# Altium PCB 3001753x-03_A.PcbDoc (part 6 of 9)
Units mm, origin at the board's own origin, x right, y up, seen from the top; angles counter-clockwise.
Board outline 210 x 130 mm, 8 copper layers (1-TOP, 2-GND, 3-INTOP, 4-PWR, 5-PWR, 6-INBOT, 7-GND, 8-BOTTOM), stack 1.646 mm thick; 676 components, 623 nets, 2861 pads, 2382 vias.
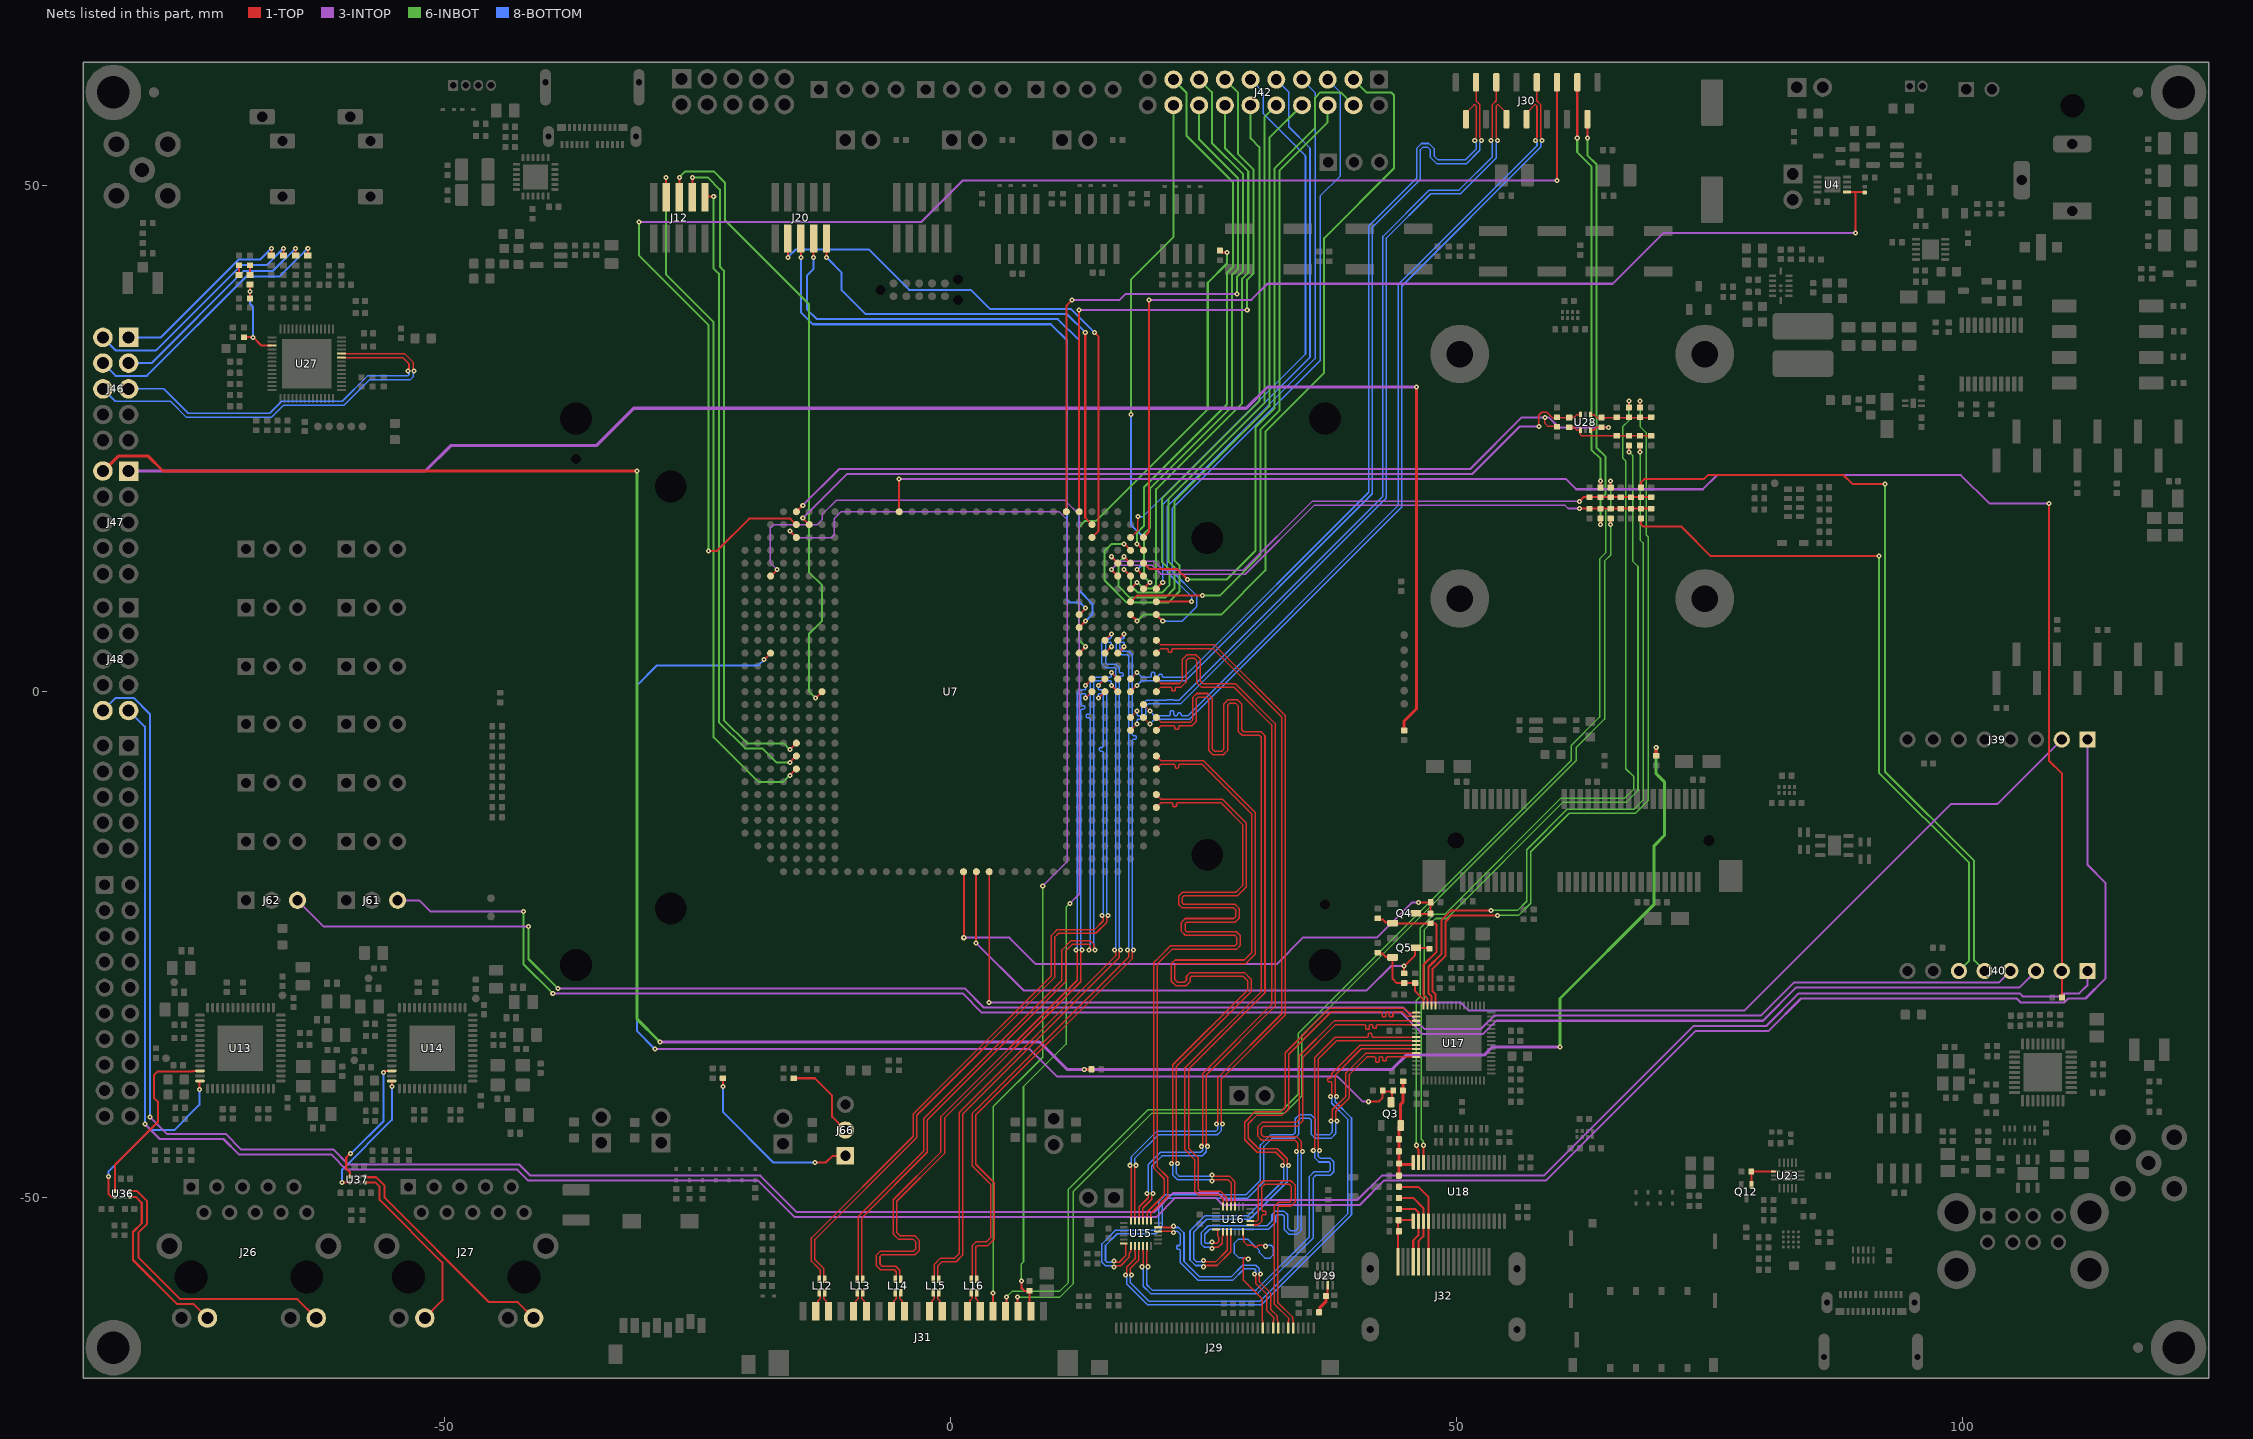
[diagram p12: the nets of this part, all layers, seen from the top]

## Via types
v1: diameter 0.5, hole 0.2, 1-TOP to 8-BOTTOM, 1547 vias
v2: diameter 0.68, hole 0.3, 1-TOP to 8-BOTTOM, 835 vias

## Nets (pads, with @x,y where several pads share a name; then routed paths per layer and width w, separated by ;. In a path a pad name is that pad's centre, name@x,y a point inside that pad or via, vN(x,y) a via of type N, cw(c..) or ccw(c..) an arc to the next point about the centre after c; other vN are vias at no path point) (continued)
HDMI_FIL_SCL: J32.15 R128.2 U18.22 | length 8.3
  1-TOP w0.2: R128.2@44.28,-50 45.7,-50 46.7,-51 U18.22@46.7,-52.3 46.7,-53.8 46.2,-54.3 J32.15@46.2,-56.3
HDMI_FIL_SDA: J32.16 R129.2 U18.21 | length 7.2
  1-TOP w0.2: R129.2@44.28,-51.1 45.9,-51.1 46.2,-51.4 U18.21@46.2,-52.3 46.2,-53.7 45.7,-54.2 J32.16@45.7,-56.3
HDMI_HPD_1V8: C115.2 Q3.S R121.1 R127.2 R130.1 R132.1 R244.1 U18.19 | length 10.9
  1-TOP w0.2: R244.1@44.28,-47.8 R244.1@44.305,-47.775
  1-TOP w0.3: R244.1@44.305,-47.775 C115.2@44.305,-46.6 44.305,-45.425 R127.2@44.28,-45.4 R130.1@44.28,-44.2 44.28,-43.02 Q3.S@44.45,-42.85 ; C115.2@44.46,-46.6 44.46,-46.7 U18.19@45.7,-46.7 ; Q3.S@44.46,-42.85 44.46,-40.74 44.7,-40.5 44.7,-39.42 R132.1@44.68,-39.4 ; R132.1@44.7,-39.4 R121.1@44.7,-38.4
HDMI_HPD_3V3_CPU: Q3.D R131.1 R132.2 U7.C18 | length 128.2
  1-TOP w0.2: v1(-18.415,3.175) U7.C18@-17.78,3.81 ; v1(41.3,-40.5) 42.3,-40.5 42.68,-40.12 R131.1@42.68,-39.5 ; R131.1@42.68,-39.4 R131.1@42.68,-39.5 ; Q3.D@43.5,-40.65 43.62,-40.53 43.62,-39.5 R131.1@42.68,-39.5
  3-INTOP w0.2: v1(-29.2,-35.3) 7.8,-35.3 10.5,-38 38.2,-38 40.7,-40.5 v1(41.3,-40.5)
  8-BOTTOM w0.2: v1(-29.2,-35.3) -31,-33.5 -31,0.6 -29,2.6 -18.99,2.6 v1(-18.415,3.175)
HDMI_SCL_1V8: R185.2 U18.17 | length 84.5
  1-TOP w0.2: U18.17@46.7,-46.5 v1(46.7,-44.8) ; v1(67,23.7) R185.2@67,24.32
  6-INBOT w0.15: v1(46.7,-44.8) 46.7,-44.4 46.5,-44.2 46.5,-30.7 46.8,-30.4 46.8,-23.5 47.9,-22.4 49,-22.4 60.5,-10.9 66.766,-10.9 67.9,-9.766 67.9,12.373 67.4,12.873 67.4,23.3 v1(67,23.7)
HDMI_SDA_1V8: R187.2 U18.18 | length 89.8
  1-TOP w0.2: v1(46,-44.8) 46,-45 46.2,-45.2 U18.18@46.2,-46.5 ; R187.2@67,28.08 v1(67,28.7)
  6-INBOT w0.15: v1(46,-44.8) 46,-30.5 46.4,-30.1 46.4,-23.334 47.734,-22 48.8,-22 60.3,-10.5 66.6,-10.5 67.5,-9.6 67.5,-8.4 66.7,-7.6 66.7,22.8 66.4,23.1 66.4,24.3 66.4,26.2 67,26.8 v1(67,28.7)
HDMICEC: J32.13 R120.2 U18.23 | length 9.7
  1-TOP w0.2: R120.2@44.28,-48.9 46.2,-48.9 47.2,-49.9 U18.23@47.2,-52.3 J32.13@47.2,-56.3
HDMIHPD: C119.2 J32.19 R126.2 U18.20 | length 5.6
  1-TOP w0.2: J32.19@44.2,-56.3 44.2,-52.26 C119.2@44.26,-52.2 45.6,-52.2 U18.20@45.7,-52.3
I2C3_SCL: R46.1 R48.1 R178.1 R180.1 R184.1 R188.1 R230.1 U7.AK25 | length 57.8
  1-TOP w0.2: v1(15.875,13.335) U7.AK25@16.51,12.7 ; v1(62.1,18.8) 62.52,19.22 R180.1@63.1,19.22 R184.1@64.2,19.22 R178.1@65.2,19.22 R188.1@66.2,19.22 R46.1@67.2,19.22 R48.1@68.2,19.22 R230.1@69.2,19.22
  3-INTOP w0.15: v1(15.875,13.335) 16.31,12.9 20.1,12.9 21,12 28.9,12 35.7,18.8 v1(62.1,18.8)
I2C3_SDA: R47.1 R49.1 R181.1 R182.1 R186.1 R190.1 R231.1 U7.AK24 | length 57.8
  1-TOP w0.2: v1(15.875,12.065) U7.AK24@16.51,11.43 ; v1(62.1,18.1) 62.12,18.08 R181.1@63.1,18.08 R186.1@64.2,18.08 64.22,18.1 65.18,18.1 R182.1@65.2,18.08 65.22,18.1 R231.1@69.2,18.1
  3-INTOP w0.15: v1(15.875,12.065) 16.31,12.5 19.9,12.5 20.8,11.6 29.1,11.6 35.9,18.4 60.7,18.4 61,18.1 v1(62.1,18.1)
I2C4_SCL: R173.1 R176.2 U7.F28 U28.6 | length 83
  1-TOP w0.15: v1(58.1,26.2) 58.1,27.3 58.4,27.6 58.9,27.6 59.42,27.08 R176.2@61.1,27.08 61.12,27.1 61.6,27.1 61.88,27.38 U28.6@62.2,27.38
  1-TOP w0.2: v1(-14.605,17.145) U7.F28@-13.97,16.51
  3-INTOP w0.2: v1(-14.605,17.145) -10.25,21.5 51.5,21.5 56.2,26.2 v1(58.1,26.2)
I2C4_SCL_1V8: R172.1 R176.1 R179.1 R185.1 R189.1 U28.1 | length 8.7
  1-TOP w0.15: R176.1@61.1,26.12 61.12,26.1 61.6,26.1 61.88,25.82 U28.1@62.2,25.82 62.2,25.4 62.32,25.28 R172.1@65.8,25.28 R185.1@67,25.28 R189.1@68.1,25.28 R179.1@69.2,25.28
I2C4_SDA: R175.1 R177.2 U7.E29 U28.3 | length 88.4
  1-TOP w0.15: v1(58.7,27.1) 58.7,26.5 59,26.2 R175.1@59.9,26.2 ; U28.3@63.2,25.82 63.52,25.82 63.82,26.12 R177.2@64.3,26.12
  1-TOP w0.2: U7.E29@-15.24,17.78 v1(-14.605,18.415) ; R177.2@64.3,26.12 64.32,26.1 v1(65,26.1)
  3-INTOP w0.2: v1(-14.605,18.415) -11.02,22 51.327,22 56.427,27.1 v1(58.7,27.1) 59.1,27.1 60.1,26.1 v1(65,26.1)
I2C4_SDA_1V8: R174.1 R177.1 R183.1 R187.1 R191.1 U28.4 | length 6.1
  1-TOP w0.15: U28.4@63.2,27.38 63.52,27.38 63.82,27.08 R177.1@64.3,27.08 65.8,27.08 67,27.08 68.1,27.08 R183.1@69.2,27.08
I3C2_SCL: J66.1 R104.1 | length 17.8
  1-TOP w0.2: v1(-22.5,-39) R104.1@-22.5,-38.18 ; v1(-13.4,-46.5) -12.314,-46.5 -11.654,-45.84 J66.1@-10.4,-45.84
  8-BOTTOM w0.2: v1(-22.5,-39) -22.5,-41.5 -17.5,-46.5 v1(-13.4,-46.5)
I3C2_SDA: J66.2 R241.1 | length 8.5
  1-TOP w0.2: R241.1@-15.5,-38.18 -13.42,-38.18 -11.7,-39.9 -11.7,-42 J66.2@-10.4,-43.3
ILIM_5V_VBUS: Q12.G R202.2 U23.6 | length 3.7
  1-TOP w0.2: Q12.G@79.1,-48.71 79.1,-47.42 R202.2@79.08,-47.4 U23.6@81.45,-47.4
IMX9_ON_OFF: R4.2 U7.AG18 | length 47.6
  1-TOP w0.2: U7.AG18@12.7,3.81 v1(13.335,4.445) ; R4.2@26.6,43.58 26.775,43.405 27.295,43.405 v1(27.3,43.4)
  6-INBOT w0.2: v1(13.335,4.445) 12.7,5.08 12.7,15.2 12.7,16.3 13.25,16.85 14.35,16.85 25.4,27.9 25.4,40.4 27.3,42.3 v1(27.3,43.4)
IW612_JTAG_TCK: J12.3 U7.E11 | length 66.4
  1-TOP w0.2: J12.3@-25.53,48.832 -25.5,48.862 v1(-25.5,50.8) ; v1(-15.875,-5.715) U7.E11@-15.24,-5.08
  6-INBOT w0.2: v1(-25.5,50.8) -24,50.8 -22.8,49.6 -22.8,42 -22.4,41.6 -22.4,-2.8 -20.1,-5.1 -16.49,-5.1 v1(-15.875,-5.715)
IW612_JTAG_TDI: J12.7 U7.E9 | length 69.8
  1-TOP w0.2: v1(-28.1,50.8) -28.1,48.862 J12.7@-28.07,48.832 ; v1(-15.875,-8.255) U7.E9@-15.24,-7.62
  6-INBOT w0.2: v1@-28.1,50.9 -28.1,41.2 -23.4,36.5 -23.4,-4.5 -19,-8.9 -16.52,-8.9 v1(-15.875,-8.255)
IW612_JTAG_TDO: J12.5 U7.G15 | length 63.8
  1-TOP w0.2: J12.5@-26.8,48.832 v1(-26.8,50.8) ; v1(-13.335,-0.635) U7.G15@-12.7,0
  6-INBOT w0.2: v1(-26.8,50.8) -26.2,51.4 -23.4,51.4 -22.3,50.3 -22.3,46.6 -14,38.3 -14,11.8 -12.7,10.5 -12.7,7 -14,5.7 -14,0.03 v1(-13.335,-0.635)
IW612_JTAG_TMS: J12.1 U7.E10 | length 62.6
  1-TOP w0.2: J12.1@-24.26,48.832 -24.26,48.9 v1(-23.4,48.9) ; v1(-15.875,-6.985) U7.E10@-15.24,-6.35
  6-INBOT w0.2: v1(-23.4,48.9) -23.4,46.6 -23.4,41.8 -22.9,41.3 -22.9,-3 -20.3,-5.6 -18.6,-5.6 -17.215,-6.985 v1(-15.875,-6.985)
JTAG_TCK: J20.4 U7.AG20 | length 64.9
  1-TOP w0.2: v1(-13.53,42.9) J20.4@-13.53,44.768 ; U7.AG20@12.7,6.35 v1(13.335,6.985)
  8-BOTTOM w0.2: v1(-13.53,42.9) -13.53,41.77 -14.2,41.1 -14.2,37.8 -13.2,36.8 10.6,36.8 12.7,34.7 12.7,10 14,8.7 14,7.65 v1(13.335,6.985)
JTAG_TDI: J20.8 U7.AH27 | length 56.6
  1-TOP w0.2: v1(-16.07,42.9) J20.8@-16.07,44.768 ; U7.AH27@13.97,15.24 14.6,15.87 14.6,35.1 v1(14.2,35.5)
  8-BOTTOM w0.2: v1(-16.07,42.9) -15.27,43.7 -8.1,43.7 -4.1,39.7 2,39.7 3.9,37.8 11.9,37.8 v1(14.2,35.5)
JTAG_TDO: J20.6 U7.AG21 | length 63.4
  1-TOP w0.2: v1(-14.8,42.9) J20.6@-14.8,44.768 ; U7.AG21@12.7,7.62 v1(13.335,8.255)
  8-BOTTOM w0.2: v1(-14.8,42.9) -14.8,41.5 -14.8,37.5 -13.6,36.3 9.9,36.3 11.5,34.7 11.5,9.1 11.8,8.8 12.79,8.8 v1(13.335,8.255)
JTAG_TMS: J20.2 U7.AH28 | length 50.8
  1-TOP w0.2: v1(-12.26,42.9) J20.2@-12.26,44.768 ; v1(13.3,35.5) 13.3,17.18 U7.AH28@13.97,16.51
  8-BOTTOM w0.2: v1(-12.26,42.9) -10.76,41.4 -10.76,39.66 -8.4,37.3 11.5,37.3 v1(13.3,35.5)
L_CLK_N: J31.11 L15.2 | length 2
  1-TOP w0.15: J31.11@-1.85,-61.25 -1.85,-60.15 -1.627,-59.927 -1.627,-59.498 L15.2@-1.725,-59.4
L_CLK_P: J31.12 L15.3 | length 2
  1-TOP w0.15: L15.3@-1.175,-59.4 -1.273,-59.498 -1.273,-59.927 -1.05,-60.15 J31.12@-1.05,-61.25
L_D0_N: J31.2 L12.2 | length 2
  1-TOP w0.15: J31.2@-13.1,-61.25 -13.1,-60.15 -12.877,-59.927 -12.877,-59.498 L12.2@-12.975,-59.4
L_D0_P: J31.3 L12.3 | length 2
  1-TOP w0.15: L12.3@-12.425,-59.4 -12.523,-59.498 -12.523,-59.927 -12.3,-60.15 J31.3@-12.3,-61.25
L_D1_N: J31.5 L13.2 | length 2
  1-TOP w0.15: J31.5@-9.35,-61.25 -9.35,-60.15 -9.127,-59.927 -9.127,-59.498 L13.2@-9.225,-59.4
L_D1_P: J31.6 L13.3 | length 2
  1-TOP w0.15: L13.3@-8.675,-59.4 -8.773,-59.498 -8.773,-59.927 -8.55,-60.15 J31.6@-8.55,-61.25
L_D2_N: J31.8 L14.2 | length 2
  1-TOP w0.15: J31.8@-5.6,-61.25 -5.6,-60.15 -5.377,-59.927 -5.377,-59.498 L14.2@-5.475,-59.4
L_D2_P: J31.9 L14.3 | length 2
  1-TOP w0.15: L14.3@-4.925,-59.4 -5.023,-59.498 -5.023,-59.927 -4.8,-60.15 J31.9@-4.8,-61.25
L_D3_N: J31.14 L16.2 | length 2
  1-TOP w0.15: J31.14@1.9,-61.25 1.9,-60.15 2.123,-59.927 2.123,-59.498 L16.2@2.025,-59.4
L_D3_P: J31.15 L16.3 | length 2
  1-TOP w0.15: L16.3@2.575,-59.4 2.477,-59.498 2.477,-59.927 2.7,-60.15 J31.15@2.7,-61.25
LDO2: J47.1 R36.1 | length 164.9
  1-TOP w0.3: R36.1@44.8,-3.82 44.8,-2.9 46,-1.7 v1(46,30.1)
  3-INTOP w0.3: J47.1@-81.1,21.82 -51.87,21.82 -49.39,24.3 -35,24.3 -31.3,28 29.2,28 31.3,30.1 v1(46,30.1)
LDO3: J47.2 R37.1 R243.1 | length 237.9
  1-TOP w0.3: J47.2@-83.64,21.82 -82.16,23.3 -79.3,23.3 -77.8,21.8 v1(-31,21.8) ; v1(13.2,-37.3) R37.1@13.92,-37.3 ; R243.1@69.7,-6.32 v1(69.7,-5.5)
  3-INTOP w0.3: v1(-28.7,-34.6) 8.8,-34.6 11.5,-37.3 v1(13.2,-37.3) 43.6,-37.3 45,-35.9 52.7,-35.9 53.5,-35.1 v1(60.2,-35.1)
  6-INBOT w0.3: v1(-31,21.8) -31,-32.3 v1(-28.7,-34.6) ; v1(60.2,-35.1) 60.2,-30.3 69.5,-21 69.5,-15.2 70.5,-14.2 70.5,-8.9 69.7,-8.1 v1(69.7,-5.5)
LED: R212.2 R217.1 U29.7 | length 3.1
  1-TOP w0.2: R212.2@36.28,-61.4 36.28,-61.32 R212.2@36.5,-61.1 ; R217.1@37.18,-59.7 37.25,-59.63 U29.7@37.25,-58.635
  1-TOP w0.3: R212.2@36.5,-61.1 36.5,-60.8 37.1,-60.2 R217.1@37.1,-59.7
LED_1_1000_1V8: U13.12 U36.4 | length 18.1
  1-TOP w0.2: U36.4@-82.55,-49.3 -82.55,-46.75 -78.3,-42.5 -78.3,-40.5 -78.7,-40.1 -78.7,-37.9 -78.3,-37.5 -74.85,-37.5 -74.8,-37.45 U13.12@-74.15,-37.45
LED_1_1000_3V3: J26.D4 U36.1 | length 28
  1-TOP w0.2: U36.1@-81.05,-49.3 -80.4,-49.3 -80.2,-49.5 -79.4,-50.3 -79.4,-52.6 -80.2,-53.4 -80.2,-55.9 -76.1,-60 -64.524,-60 J26.D4@-62.66,-61.864
LED_1_ACT_1V8: U13.14 U36.5 | length 17.1
  1-TOP w0.2: v1@-83.156,-47.944 v1(-83.2,-47.9) -83.2,-49.6 -82.9,-49.9 U36.5@-82.55,-49.9 ; v1(-74.2,-39.3) -74.2,-38.5 U13.14@-74.15,-38.45
  8-BOTTOM w0.2: v1(-83.2,-47.9) -83.2,-47.4 -79.1,-43.3 -76.7,-43.3 -74.2,-40.8 v1(-74.2,-39.3)
LED_1_ACT_3V3: J26.D2 U36.8 | length 17.1
  1-TOP w0.2: U36.8@-81.05,-49.9 -80.5,-49.9 -79.9,-50.5 -79.9,-52.5 -80.766,-53.366 -80.766,-56.134 -76.4,-60.5 -74.774,-60.5 J26.D2@-73.41,-61.864
LED_2_1000_1V8: U14.12 U37.4 | length 12.9
  1-TOP w0.2: U37.4@-59.35,-47.9 -59.35,-47.445 -59.7,-47.095 -59.7,-46 v1(-59.3,-45.6) ; v1(-56,-37.6) -55.85,-37.45 U14.12@-55.2,-37.45
  8-BOTTOM w0.2: v1(-59.3,-45.6) -59.219,-45.6 -59.08,-45.461 -59.061,-45.461 -56,-42.4 v1(-56,-37.6)
LED_2_1000_3V3: J27.D4 U37.1 | length 23.2
  1-TOP w0.2: U37.1@-57.85,-47.9 -57.85,-47.91 -57.8,-47.96 -56.74,-47.96 -55.9,-48.8 -55.9,-50 -45.6,-60.3 -42.754,-60.3 J27.D4@-41.19,-61.864
LED_2_ACT_1V8: U14.14 U37.5 | length 12.8
  1-TOP w0.2: v1(-60.1,-48.5) U37.5@-59.35,-48.5 ; v1(-55.2,-39) U14.14@-55.2,-38.45
  8-BOTTOM w0.2: v1(-60.1,-48.5) -60.1,-47.2 -55.2,-42.3 v1(-55.2,-39)
LED_2_ACT_3V3: J27.D2 U37.8 | length 17.9
  1-TOP w0.2: U37.8@-57.85,-48.5 -56.8,-48.5 -56.4,-48.9 -56.4,-50.2 -50.2,-56.4 -50.2,-60.124 J27.D2@-51.94,-61.864
LINE1_IN_L: J46.2 L35.1 | length 23.3
  1-TOP w0.2: L35.1@-65.9,43.08 v1(-65.9,43.8)
  8-BOTTOM w0.2: J46.2@-83.74,35 -82.44,33.7 -78.5,33.7 -70.069,42.131 -67.569,42.131 v1(-65.9,43.8)
LINE1_IN_R: J46.1 L34.1 | length 18.5
  1-TOP w0.2: L34.1@-67.1,43.08 v1(-67.1,43.8)
  8-BOTTOM w0.2: J46.1@-81.2,35 -78,35 -70.303,42.697 -68.203,42.697 v1(-67.1,43.8)
LINE2_IN_L: J46.4 L37.1 | length 26.7
  1-TOP w0.2: L37.1@-63.5,43.08 v1(-63.5,43.8)
  8-BOTTOM w0.2: J46.4@-83.74,32.46 -82.48,31.2 -79.4,31.2 -69.6,41 -66.3,41 v1(-63.5,43.8)
LINE2_IN_R: J46.3 L36.1 | length 21.9
  1-TOP w0.2: L36.1@-64.7,43.08 v1(-64.7,43.8)
  8-BOTTOM w0.2: J46.3@-81.2,32.46 -78.94,32.46 -69.834,41.566 -66.934,41.566 v1(-64.7,43.8)
LINE_OUT_L: J46.6 U27.24 | length 42.4
  1-TOP w0.15: U27.24@-60.17,33.4 -59,33.4 -53.934,33.4 -53.1,32.566 -53.1,31.8 v1(-53,31.7)
  8-BOTTOM w0.15: J46.6@-83.74,29.92 -82.52,28.7 -77.066,28.7 -75.466,27.1 -67.1,27.1 -65.9,28.3 -59.934,28.3 -57.434,30.8 -53.4,30.8 -53.1,31.1 -53.1,31.6 v1(-53,31.7)
LINE_OUT_R: J46.5 U27.23 | length 38.4
  1-TOP w0.15: U27.23@-60.17,33 -54.1,33 -53.5,32.4 -53.5,31.8 v1(-53.6,31.7)
  8-BOTTOM w0.15: J46.5@-81.2,29.92 -77.72,29.92 -75.3,27.5 -67.266,27.5 -66.066,28.7 -60.1,28.7 -57.6,31.2 -53.6,31.2 -53.5,31.3 -53.5,31.6 v1(-53.6,31.7)
LT8912B_CLK_N: U15.16 U17.8 | length 54.6
  1-TOP w0.15: v1(18.9,-56.8) 19.023,-56.677 19.023,-55.323 19,-55.3 U15.16@19,-54.745 ; v1(36.423,-45.3) 36.3,-45.177 36.3,-36.301 38.124,-34.477 45.972,-34.477 U17.8@45.995,-34.5
  8-BOTTOM w0.15: v1(18.9,-56.8) 19.023,-56.923 19.023,-58.723 19.754,-59.454 ; 19.78,-59.454 30.322,-59.454 35.8,-53.976 35.8,-48.026 36.072,-47.754 37.512,-47.754 37.85,-47.416 37.85,-46.422 37.528,-46.1 36.525,-46.1 36.3,-45.875 36.3,-45.423 v1(36.423,-45.3)
LT8912B_CLK_P: U15.17 U17.7 | length 54.6
  1-TOP w0.15: U15.17@19.4,-54.745 19.4,-55.3 19.377,-55.323 19.377,-56.677 v1(19.5,-56.8) ; v1(35.823,-45.3) 35.946,-45.177 35.946,-36.154 37.977,-34.123 41.1,-34.123 41.175,-34.123 41.263,-34.035 41.263,-33.807 41.333,-33.737 41.543,-33.737 41.613,-33.807 41.613,-34.035 41.701,-34.123 41.8,-34.123 43.6,-34.123 45.972,-34.123 U17.7@45.995,-34.1
  8-BOTTOM w0.15: v1(19.5,-56.8) 19.377,-56.923 19.377,-58.576 19.901,-59.1 ; 19.926,-59.1 30.175,-59.1 35.446,-53.829 35.446,-47.879 35.925,-47.4 37.365,-47.4 37.496,-47.269 37.496,-46.569 37.381,-46.454 36.378,-46.454 35.946,-46.022 35.946,-45.423 v1(35.823,-45.3)
LT8912B_D0_N: U16.14 U17.2 | length 54.6
  1-TOP w0.15: v1(25,-56.2) 25.123,-56.323 26.176,-56.323 27.323,-55.176 27.323,-53.827 27.321,-53.825 27.321,-53.366 U16.14@27.3,-53.345 ; v1(33.377,-46.8) 33.254,-46.677 33.254,-46.129 32.271,-45.146 30.446,-45.146 29.4,-44.1 29.4,-42.676 30.222,-41.854 32.746,-41.854 33.4,-41.2 33.4,-35.801 37.597,-31.604 42.136,-31.604 42.561,-31.604 42.649,-31.692 42.649,-32.074 42.701,-32.126 42.946,-32.126 42.999,-32.074 42.999,-31.657 43.051,-31.604 43.296,-31.604 43.349,-31.657 43.349,-32.056 43.401,-32.109 43.646,-32.109 43.699,-32.056 43.699,-31.692 43.787,-31.604 44.25,-31.604 44.63,-31.604 45.103,-32.077 45.972,-32.077 U17.2@45.995,-32.1
  8-BOTTOM w0.15: v1(25,-56.2) 24.877,-56.323 24.323,-56.323 24,-56 24,-53.4 25.3,-52.1 29.55,-52.1 33.254,-48.396 33.254,-46.923 v1(33.377,-46.8)
LT8912B_D0_P: U16.15 U17.1 | length 54.6
  1-TOP w0.15: v1(25,-56.8) 25.123,-56.677 26.323,-56.677 27.677,-55.323 27.677,-53.368 U16.15@27.7,-53.345 ; v1(32.777,-46.8) 32.9,-46.677 32.9,-46.276 32.124,-45.5 30.299,-45.5 29.046,-44.247 29.046,-42.529 30.075,-41.5 32.599,-41.5 33.046,-41.053 33.046,-35.654 37.45,-31.25 44.777,-31.25 45.25,-31.723 45.972,-31.723 U17.1@45.995,-31.7
  8-BOTTOM w0.15: v1(25,-56.8) 24.877,-56.677 24.176,-56.677 23.646,-56.147 23.646,-53.253 25.153,-51.746 29.403,-51.746 32.9,-48.249 32.9,-46.923 v1(32.777,-46.8)
LT8912B_D1_N: U16.12 U17.4 | length 54.5
  1-TOP w0.15: v1(25.8,-54.377) 25.8,-54.4 25.9,-54.5 26.299,-54.5 26.473,-54.326 26.473,-53.873 26.4,-53.8 U16.12@26.4,-53.1 ; v1(34.777,-45.4) 34.654,-45.277 34.654,-44.429 34.171,-43.946 30.878,-43.946 30.675,-43.743 30.675,-43.136 30.911,-42.9 34.275,-42.9 34.8,-42.375 34.8,-36.101 38.024,-32.877 40.5,-32.877 40.925,-32.877 41.013,-32.965 41.013,-33.292 41.065,-33.345 41.31,-33.345 41.363,-33.292 41.363,-32.929 41.415,-32.877 41.66,-32.877 41.713,-32.929 41.713,-33.197 41.765,-33.249 42.01,-33.249 42.063,-33.197 42.063,-32.965 42.151,-32.877 42.25,-32.877 43.8,-32.877 45.972,-32.877 U17.4@45.995,-32.9
  8-BOTTOM w0.15: v1(25.8,-54.377) 25.677,-54.5 25.2,-54.5 25.1,-54.4 25.1,-53.601 25.601,-53.1 29.5,-53.1 31.401,-53.1 32.1,-52.401 32.1,-51.801 32.247,-51.654 32.79,-51.654 32.946,-51.81 32.946,-53.119 33.427,-53.6 34.229,-53.6 34.654,-53.175 34.654,-51.947 34.654,-45.523 v1(34.777,-45.4)
LT8912B_D1_P: U16.13 U17.3 | length 54.6
  1-TOP w0.15: v1(25.8,-54.977) 25.8,-54.954 25.9,-54.854 26.173,-54.854 26.446,-54.854 26.827,-54.473 26.827,-53.873 26.9,-53.8 U16.13@26.9,-53.345 ; v1(34.177,-45.4) 34.3,-45.277 34.3,-44.576 34.024,-44.3 30.731,-44.3 30.321,-43.89 30.321,-42.989 30.764,-42.546 34.128,-42.546 34.446,-42.228 34.446,-35.954 37.877,-32.523 45.972,-32.523 U17.3@45.995,-32.5
  8-BOTTOM w0.15: v1(25.8,-54.977) 25.677,-54.854 25.053,-54.854 24.746,-54.547 24.746,-53.454 25.454,-52.746 31.254,-52.746 31.746,-52.254 31.746,-51.654 32.1,-51.3 32.937,-51.3 33.3,-51.663 33.3,-52.972 33.574,-53.246 34.082,-53.246 34.3,-53.028 34.3,-45.523 v1(34.177,-45.4)
LT8912B_D2_N: U15.14 U17.10 | length 54.6
  1-TOP w0.15: v1(17.277,-57.6) 17.4,-57.477 17.4,-56.823 18.223,-56 18.223,-55.323 18.2,-55.3 U15.14@18.2,-54.745 ; v1(38.123,-40) 38,-39.877 38,-37.85 40.573,-35.277 43.6,-35.277 45.972,-35.277 U17.10@45.995,-35.3
  8-BOTTOM w0.15: v1(17.277,-57.6) 17.4,-57.723 17.4,-58.501 19.453,-60.554 ; 19.479,-60.554 30.721,-60.554 39.6,-51.675 39.6,-42.099 38,-40.499 38,-40.123 v1(38.123,-40)
LT8912B_D2_P: U15.15 U17.9 | length 54.6
  1-TOP w0.15: v1(17.877,-57.6) 17.754,-57.477 17.754,-56.97 18.577,-56.147 18.577,-55.323 18.6,-55.3 U15.15@18.6,-54.745 ; v1(37.523,-40) 37.646,-39.877 37.646,-38.605 37.558,-38.517 37.33,-38.517 37.26,-38.447 37.26,-38.237 37.33,-38.167 37.558,-38.167 37.646,-38.079 37.646,-37.9 37.646,-37.703 40.426,-34.923 45.972,-34.923 U17.9@45.995,-34.9
  8-BOTTOM w0.15: v1(17.877,-57.6) 17.754,-57.723 17.754,-58.354 19.6,-60.2 ; 19.626,-60.2 30.574,-60.2 39.246,-51.528 39.246,-42.246 37.646,-40.646 37.646,-40.123 v1(37.523,-40)
LT8912B_D3_N: U15.12 U17.12 | length 54.5
  1-TOP w0.15: v1(16.154,-56.223) 16.154,-56.246 16.254,-56.346 16.654,-56.346 17.3,-55.7 U15.12@17.3,-54.5 ; v1(38.177,-42.423) 38.054,-42.3 38.054,-41.447 39.4,-40.101 39.4,-37.8 41.123,-36.077 41.475,-36.077 41.8,-36.077 41.9,-36.077 41.988,-36.165 41.988,-36.524 42.04,-36.577 42.285,-36.577 42.338,-36.524 42.338,-36.129 42.39,-36.077 42.635,-36.077 42.688,-36.129 42.688,-36.396 42.74,-36.449 42.985,-36.449 43.038,-36.396 43.038,-36.165 43.126,-36.077 43.175,-36.077 43.25,-36.077 44.022,-36.077 45.972,-36.077 U17.12@45.995,-36.1
  8-BOTTOM w0.15: v1(16.154,-56.223) 16.031,-56.346 15.446,-56.346 15.3,-56.2 15.3,-54.7 16.466,-53.534 20.291,-53.534 20.904,-52.921 20.904,-50.497 21.347,-50.054 29.296,-50.054 30.954,-48.396 30.954,-44.922 31.747,-44.129 33.972,-44.129 34.4,-43.701 34.4,-42.32 34.566,-42.154 35.466,-42.154 35.646,-42.334 35.646,-43.747 36.028,-44.129 37.572,-44.129 38.054,-43.647 38.054,-42.546 v1(38.177,-42.423)
LT8912B_D3_P: U15.13 U17.11 | length 54.6
  1-TOP w0.15: v1(16.154,-56.823) 16.154,-56.8 16.254,-56.7 16.801,-56.7 17.654,-55.847 17.654,-55.446 17.8,-55.3 U15.13@17.8,-54.745 ; v1(37.577,-42.423) 37.7,-42.3 37.7,-41.3 39.046,-39.954 39.046,-37.653 40.976,-35.723 45.972,-35.723 U17.11@45.995,-35.7
  8-BOTTOM w0.15: v1(16.154,-56.823) 16.031,-56.7 15.299,-56.7 14.946,-56.347 14.946,-54.553 16.319,-53.18 20.144,-53.18 20.55,-52.774 20.55,-50.35 21.2,-49.7 29.149,-49.7 30.6,-48.249 30.6,-44.775 31.6,-43.775 33.825,-43.775 34.046,-43.554 34.046,-42.174 34.42,-41.8 35.613,-41.8 36,-42.187 36,-43.6 36.175,-43.775 37.425,-43.775 37.7,-43.5 37.7,-42.546 v1(37.577,-42.423)
LT8912B_INT_1V8: Q4.S R133.1 R135.1 U17.63 | length 14.5
  1-TOP w0.15: Q4.S@43.655,-22.85 Q4.S@43.685,-22.88
  1-TOP w0.2: R133.1@42.305,-22.48 42.685,-22.48 43.005,-22.8 Q4.S@43.605,-22.8 ; Q4.S@43.685,-22.88 R135.1@47.405,-22.88 47.88,-22.88 48,-23 48,-25.7 46.705,-26.995 46.705,-29.9 47.1,-30.295 U17.63@47.1,-30.995
LT8912B_INT_3V3: Q4.D R134.1 R135.2 U7.V1 | length 59.1
  1-TOP w0.2: U7.V1@1.27,-17.78 1.3,-17.81 v1(1.3,-24.3) ; Q4.D@45.735,-21.68 Q4.D@45.955,-21.9 ; Q4.D@46.005,-21.95 R135.2@47.375,-21.95 ; v1(46.2,-20.8) R134.1@47.42,-20.8 R135.2@47.42,-21.905
  1-TOP w0.3: R135.2@47.375,-21.95 R135.2@47.405,-21.92 R135.2@47.42,-21.905
  3-INTOP w0.2: v1(1.3,-24.3) 5.8,-24.3 8.4,-26.9 32.2,-26.9 34.8,-24.3 42.1,-24.3 45.6,-20.8 v1(46.2,-20.8)
LT8912B_RST_1V8: Q5.S R122.2 R136.1 R138.1 U17.64 | length 8.5
  1-TOP w0.2: R136.1@42.305,-25.88 42.685,-25.88 43.005,-26.2 Q5.S@43.605,-26.2 ; Q5.S@43.655,-26.25 43.655,-28.355 44.08,-28.78 R138.1@44.8,-28.78 R122.2@45.9,-28.78 ; R122.2@45.885,-28.8 45.885,-29.58 46.7,-30.395 U17.64@46.7,-30.995
LT8912B_RST_3V3: Q5.D R137.1 R138.2 U7.W1 | length 56.8
  1-TOP w0.2: v1(2.5,-24.8) 2.5,-17.82 U7.W1@2.54,-17.78 ; v1@44.7,-27.2 v1(44.8,-27.1) ; R138.2@44.8,-27.82 v1(44.8,-27.1) ; R137.1@47.305,-25.38 47.225,-25.3 Q5.D@45.955,-25.3 45.885,-25.37 45.885,-26.015 v1(44.8,-27.1)
  3-INTOP w0.2: v1(2.5,-24.8) 7.2,-29.5 41.1,-29.5 43.5,-27.1 v1(44.8,-27.1)
LT8912B_SCL: R189.2 U17.62 | length 72.1
  1-TOP w0.2: U17.62@47.5,-30.995 47.5,-30.095 47.205,-29.8 47.205,-27.195 48.5,-25.9 48.5,-22.534 49.434,-21.6 v1(53.4,-21.6) ; v1(68.1,23.7) R189.2@68.1,24.32
  6-INBOT w0.15: v1(53.4,-21.6) 56,-21.6 56.9,-20.7 56.9,-15.6 60.9,-11.6 67.5,-11.6 68.4,-10.7 68.4,14.7 68.1,15 v1(68.1,23.7)
LT8912B_SDA: R191.2 U17.61 | length 77.3
  1-TOP w0.2: U17.61@47.9,-30.995 47.9,-29.895 47.605,-29.6 47.605,-27.361 48.9,-26.066 48.9,-22.7 49.5,-22.1 v1(54,-22.1) ; R191.2@68.1,28.08 v1(68.1,28.7)
  6-INBOT w0.15: v1(54,-22.1) 56.1,-22.1 57.3,-20.9 57.3,-15.8 61.1,-12 67.666,-12 68.9,-10.766 68.9,12.1 68.9,15.3 68.7,15.5 68.7,25.6 68.1,26.2 v1(68.1,28.7)
LVDS_CLK_N: L15.1 U7.AJ19 | length 74.8
  1-TOP w0.15: L15.1@-1.725,-58.05 -1.627,-57.952 -1.627,-56.576 -0.997,-55.946 0.403,-55.946 0.846,-55.503 0.846,-41.553 16.3,-26.099 16.3,-25.623 v1(16.177,-25.5) ; U7.AJ19@15.24,5.08 v1(15.875,5.715)
  8-BOTTOM w0.15: v1(15.875,5.715) 15.873,5.713 15.873,5.345 15.786,5.257 15.301,5.257 14.95,4.906 14.95,2.742 15.346,2.346 16.2,2.346 16.3,2.246 16.3,-25.377 v1(16.177,-25.5)
LVDS_CLK_P: L15.4 U7.AJ18 | length 74.8
  1-TOP w0.15: L15.4@-1.175,-58.05 -1.273,-57.952 -1.273,-56.723 -0.85,-56.3 0.55,-56.3 1.2,-55.65 1.2,-41.7 16.654,-26.246 16.654,-25.623 v1(16.777,-25.5) ; U7.AJ18@15.24,3.81 v1(15.875,4.445)
  8-BOTTOM w0.15: v1(15.875,4.445) 15.873,4.447 15.873,4.815 15.786,4.903 15.447,4.903 15.304,4.76 15.304,2.889 15.493,2.7 16.347,2.7 16.654,2.393 16.654,1.954 16.742,1.866 16.969,1.866 17.039,1.796 17.039,1.586 16.969,1.516 16.742,1.516 16.654,1.428 16.654,-25.377 v1(16.777,-25.5)
LVDS_D0_N: L12.1 U7.AJ15 | length 74.8
  1-TOP w0.15: L12.1@-12.975,-58.05 -12.877,-57.952 -12.877,-57.123 -13.2,-56.8 -13.754,-56.246 -13.754,-53.953 -3.7,-43.899 -3.7,-41.699 -0.204,-38.203 ; -0.2,-38.2 9.954,-28.045 9.954,-24.07 10.524,-23.5 14.2,-23.5 15.08,-22.62 15.08,-22.246 v1(14.957,-22.123) ; v1(14.605,-0.635) U7.AJ15@15.24,0
  8-BOTTOM w0.15: v1(14.605,-0.635) 14.605,-0.252 14.68,-0.177 14.957,-0.177 15.08,-0.3 15.08,-5.421 14.992,-5.509 14.764,-5.509 14.694,-5.579 14.694,-5.789 14.764,-5.859 14.992,-5.859 15.08,-5.947 15.08,-22 v1(14.957,-22.123)
LVDS_D0_P: L12.4 U7.AJ16 | length 74.8
  1-TOP w0.15: L12.4@-12.425,-58.05 -12.523,-57.952 -12.523,-56.976 -13.053,-56.446 -13.4,-56.099 -13.4,-54.1 -3.346,-44.046 -3.346,-41.846 10.308,-28.192 10.308,-24.217 10.671,-23.854 14.347,-23.854 15.434,-22.767 15.434,-22.246 v1(15.557,-22.123) ; v1(14.605,0.635) U7.AJ16@15.24,1.27
  8-BOTTOM w0.15: v1(14.605,0.635) 14.605,0.252 14.68,0.177 15.104,0.177 15.434,-0.153 15.434,-22 v1(15.557,-22.123)
LVDS_D1_N: L13.1 U7.AK15 | length 74.8
  1-TOP w0.15: L13.1@-9.225,-58.05 -9.127,-57.952 -9.127,-51.827 -2.654,-45.354 -2.654,-42.153 11,-28.499 11,-25.499 11.899,-24.6 13.801,-24.6 14.125,-24.924 14.125,-25.282 14.248,-25.405 v1(14.248,-25.5) ; v1(15.875,0.635) U7.AK15@16.51,0
  8-BOTTOM w0.15: v1(14.248,-25.5) 14.125,-25.377 14.125,0.925 14.293,1.093 15.8,1.093 15.875,1.018 v1(15.875,0.635)
LVDS_D1_P: L13.4 U7.AK16 | length 74.8
  1-TOP w0.15: L13.4@-8.675,-58.05 -8.773,-57.952 -8.773,-51.974 -2.3,-45.501 -2.3,-42.3 11.354,-28.646 11.354,-25.646 12.046,-24.954 13.654,-24.954 13.771,-25.071 13.771,-25.282 13.648,-25.405 v1(13.648,-25.5) ; v1(15.875,1.905) U7.AK16@16.51,1.27
  8-BOTTOM w0.15: v1(13.648,-25.5) 13.771,-25.377 13.771,-2.643 13.701,-2.573 13.465,-2.573 13.395,-2.503 13.395,-2.293 13.465,-2.223 13.701,-2.223 13.771,-2.153 13.771,1.072 14.146,1.447 15.8,1.447 15.875,1.522 v1(15.875,1.905)
LVDS_D2_N: L14.1 U7.AH16 | length 74.8
  1-TOP w0.15: L14.1@-5.475,-58.05 -5.377,-57.952 -5.377,-57.3 -5.577,-57.1 -6.925,-57.1 -7.329,-56.696 -7.329,-55.653 -6.922,-55.246 -3.647,-55.246 -3.429,-55.028 -3.429,-54.346 -3.675,-54.1 -5.15,-54.1 -5.675,-53.575 -5.675,-50.175 -0.954,-45.454 -0.954,-41.953 12.506,-28.493 12.506,-25.623 v1(12.383,-25.5) ; v1(13.335,0.635) U7.AH16@13.97,1.27
  8-BOTTOM w0.15: v1(12.383,-25.5) 12.506,-25.377 12.506,-0.153 12.836,0.177 13.26,0.177 13.335,0.252 v1(13.335,0.635)
LVDS_D2_P: L14.4 U7.AH15 | length 74.8
  1-TOP w0.15: L14.4@-4.925,-58.05 -5.023,-57.952 -5.023,-57.153 -5.43,-56.746 -6.778,-56.746 -6.975,-56.549 -6.975,-55.8 -6.775,-55.6 -3.5,-55.6 -3.075,-55.175 -3.075,-54.199 -3.528,-53.746 -5.003,-53.746 -5.321,-53.428 -5.321,-50.322 -0.6,-45.601 -0.6,-42.1 12.86,-28.64 12.86,-25.623 v1(12.983,-25.5) ; v1(13.335,-0.635) U7.AH15@13.97,0
  8-BOTTOM w0.15: v1(12.983,-25.5) 12.86,-25.377 12.86,-1.783 12.93,-1.713 13.171,-1.713 13.241,-1.643 13.241,-1.433 13.171,-1.363 12.948,-1.363 12.86,-1.275 12.86,-0.3 12.983,-0.177 13.26,-0.177 13.335,-0.252 v1(13.335,-0.635)
LVDS_D3_N: L16.1 U7.AK19 | length 74.8
  1-TOP w0.15: L16.1@2.025,-58.05 2.123,-57.952 2.123,-54.727 2.497,-54.353 3.522,-54.353 3.946,-53.929 3.946,-48.646 2.123,-46.823 2.123,-41.676 2.696,-41.103 ; 2.7,-41.1 17.6,-26.199 v1@17.6,-25.623 ; U7.AK19@16.51,5.08 v1(17.145,5.715) ; v1(17.477,-25.5) 17.5,-25.5 v1@17.6,-25.6
  8-BOTTOM w0.15: v1(17.145,5.715) 17.145,5.332 17.07,5.257 16.653,5.257 16.346,4.95 16.346,4.153 16.853,3.646 17.454,3.646 17.6,3.5 17.6,-25.377 v1(17.477,-25.5)
LVDS_D3_P: L16.4 U7.AK18 | length 74.8
  1-TOP w0.15: L16.4@2.575,-58.05 2.477,-57.952 2.477,-54.874 2.644,-54.707 3.669,-54.707 4.3,-54.076 4.3,-48.499 2.477,-46.676 2.477,-41.823 17.954,-26.346 v1@17.954,-25.623 ; U7.AK18@16.51,3.81 v1(17.145,4.445) ; v1@17.954,-25.6 18.054,-25.5 v1(18.077,-25.5)
  8-BOTTOM w0.15: v1(17.145,4.445) 17.145,4.828 17.07,4.903 16.8,4.903 16.7,4.803 16.7,4.3 17,4 17.601,4 17.954,3.647 17.954,-4.249 18.042,-4.337 18.269,-4.337 18.339,-4.407 18.339,-4.617 18.269,-4.687 18.042,-4.687 17.954,-4.775 17.954,-25.377 v1(18.077,-25.5)
LVDS_I2C_SCL: J31.17 R178.2 | length 117.9
  1-TOP w0.2: J31.17@5.425,-61.2 5.5,-61.125 v1(5.5,-59.8) ; R178.2@65.2,20.18 v1(65.2,20.8)
  6-INBOT w0.15: v1(5.5,-59.8) 6.1,-59.2 10.8,-59.2 11.6,-58.4 11.6,-49.2 19.5,-41.3 32.8,-41.3 34.346,-39.754 34.346,-33.754 61.3,-6.8 61.3,-5.3 64.1,-2.5 64.1,13.107 64.7,13.707 64.7,17.9 65.2,18.4 v1(65.2,20.8)
LVDS_I2C_SDA: J31.18 R182.2 | length 112.8
  1-TOP w0.2: v1(6.6,-59.8) 6.6,-61.125 J31.18@6.675,-61.2 ; v1(65.2,16.5) R182.2@65.2,17.12
  6-INBOT w0.15: v1(6.6,-59.8) 10.8,-59.8 12.1,-58.5 12.1,-49.4 19.846,-41.654 32.946,-41.654 34.7,-39.9 34.7,-33.9 61.8,-6.8 61.8,-5.5 64.6,-2.7 64.6,12.9 65.2,13.5 v1(65.2,16.5)
LVDS_IRQ_N: J31.19 R118.2 U7.C24 | length 119.5
  1-TOP w0.2: U7.C24@-17.78,11.43 v1(-17.145,12.065) ; v1(7,-58.2) 7,-58.9 7.28,-59.18 R118.2@7.8,-59.18 7.8,-61.075 J31.19@7.925,-61.2
  3-INTOP w0.15: v1(-17.145,12.065) -17.8,12.72 -17.8,16.2 -17.5,16.5 -13.2,16.5 -12.7,17 -12.7,17.5 -11.3,18.9 11.3,18.9 12.7,17.5 12.7,-19.9 12.7,-20 v1(11.8,-20.9)
  6-INBOT w0.15: v1(7,-58.2) 7,-56.5 7.2,-56.3 7.2,-39 11.4,-34.8 11.4,-21.3 v1(11.8,-20.9)
LVDS_PWM_OUT: J31.16 U7.E27 | length 112.1
  1-TOP w0.2: v1(-15.875,15.875) U7.E27@-15.24,15.24 ; J31.16@4.175,-61.2 4.2,-61.175 v1(4.2,-59.4)
  3-INTOP w0.15: v1(-15.875,15.875) -15.2,15.2 -11.8,15.2 -11.5,15.5 -11.5,17.1 -10.8,17.8 10.7,17.8 11.5,17 11.5,-16.8 v1(9.1,-19.2)
  6-INBOT w0.15: v1(4.2,-59.4) 4.2,-41 9.1,-36.1 v1(9.1,-19.2)
MCA_CLKOUT32K: J42.3 U7.AL21 | length 72.5
  1-TOP w0.2: U7.AL21@17.78,7.62 v1(18.415,6.985)
  6-INBOT w0.2: v1(18.415,6.985) 19.05,7.62 26.72,7.62 31.1,12 31.1,25.7 36.9,31.5 36.9,44.8 43.8,51.7 43.8,58.9 43.5,59.2 41.06,59.2 J42.3@39.79,60.47
MCA_IO9: J42.13 U7.AG29 | length 60.7
  1-TOP w0.2: U7.AG29@12.7,17.78 v1(12.7,37.7)
  3-INTOP w0.2: v1(12.7,37.7) v1(29.3,37.7)
  6-INBOT w0.2: J42.13@27.09,60.47 28.4,59.16 28.4,53.1 29.9,51.6 29.9,41.3 29.3,40.7 v1(29.3,37.7)
MCA_IO10: J42.15 U7.AF29 | length 60.9
  1-TOP w0.2: U7.AF29@11.43,17.78 11.43,38.13 v1(12,38.7)
  3-INTOP w0.2: v1(12,38.7) 16.7,38.7 17.3,39.3 v1(28.3,39.3)
  6-INBOT w0.2: J42.15@24.55,60.47 25.8,59.22 25.8,54.2 28.9,51.1 28.9,41.6 28.3,41 v1(28.3,39.3)
MCA_IO11: J42.17 U7.AM26 | length 53.1
  1-TOP w0.2: v1(18.415,14.605) U7.AM26@19.05,13.97
  6-INBOT w0.2: v1(18.415,14.605) 18.415,15.715 19.1,16.4 19.1,20.207 27.3,28.407 27.3,41.407 27.9,42.007 27.9,50.3 23.3,54.9 23.3,59.18 J42.17@22.01,60.47
MCA_IO12: J42.4 U7.AM25 | length 64.6
  1-TOP w0.2: U7.AM25@19.05,12.7 19.65,12.1 22.4,12.1 v1(23.4,11.1)
  6-INBOT w0.2: v1(23.4,11.1) 27.3,11.1 30.1,13.9 30.1,26.1 32,28 32,51.7 36,55.7 36,58.692 36.508,59.2 38.52,59.2 J42.4@39.79,57.93
MCA_IO13: J42.6 U7.AL22 | length 61.9
  1-TOP w0.2: U7.AL22@17.78,8.89 18.39,9.5 v1(24.9,9.5)
  6-INBOT w0.2: v1(24.9,9.5) 26.6,9.5 30.6,13.5 30.6,25.893 32.5,27.793 32.5,51.5 37.25,56.25 J42.6@37.25,57.93
MCA_IO14: J42.8 U7.AL26 | length 68.3
  1-TOP w0.2: v1(17.145,14.605) U7.AL26@17.78,13.97
  6-INBOT w0.2: v1(17.145,14.605) 15.905,14.605 15.2,13.9 15.2,11 17.4,8.8 21.5,8.8 22.6,9.9 22.6,12.5 22.1,13 22.1,18.8 31.495,28.195 31.495,54.715 J42.8@34.71,57.93
MCA_IO15: J42.10 U7.AL25 | length 62.8
  1-TOP w0.15: v1(17.145,13.335) U7.AL25@17.78,12.7
  6-INBOT w0.2: v1(17.145,13.335) 16.6,12.79 16.6,10.4 17.7,9.3 21.2,9.3 22.1,10.2 22.1,12.3 21.5,12.9 21.5,19 31,28.5 31,56.76 J42.10@32.17,57.93
MCA_IO16: J42.12 U7.AL24 | length 59.2
  1-TOP w0.2: v1(17.145,12.065) U7.AL24@17.78,11.43
  6-INBOT w0.2: v1(17.145,12.065) 17.8,11.41 17.8,10.5 18.5,9.8 20.9,9.8 21.6,10.5 21.6,12.1 20.9,12.8 20.9,19.1 30.5,28.7 30.5,53.8 29.63,54.67 J42.12@29.63,57.93
MCA_IO17: J42.14 U7.AL23 | length 55.3
  1-TOP w0.2: U7.AL23@17.78,10.16 v1(18.415,10.795)
  6-INBOT w0.2: v1(18.415,10.795) 19.01,10.2 19.9,10.2 20.3,10.6 20.3,20 28.8,28.5 28.8,40.8 29.4,41.4 29.4,51.4 27.09,53.71 J42.14@27.09,57.93
MCA_IO18: J42.16 U7.AM23 | length 53.7
  1-TOP w0.2: U7.AM23@19.05,10.16 v1(19.685,10.795)
  6-INBOT w0.2: v1(19.685,10.795) 19.1,11.38 19.1,15.6 19.7,16.2 19.7,20.1 27.8,28.2 27.8,41.2 28.4,41.8 28.4,50.7 24.55,54.55 J42.16@24.55,57.93
MCA_UART_CTS: J42.9 U7.AN23 | length 58
  1-TOP w0.2: U7.AN23@20.32,10.16 v1(20.955,10.795)
  8-BOTTOM w0.15: v1(20.955,10.795) 20.955,18.491 35.5,33.036 35.5,53.7 33.4,55.8 33.4,59.24 J42.9@32.17,60.47
MCA_UART_RTS: J42.11 U7.AL27 | length 54.9
  1-TOP w0.15: U7.AL27@17.78,15.24 18.5,15.96 v1(18.5,17.3)
  8-BOTTOM w0.15: v1(18.5,17.3) 19,17.3 35.055,33.355 35.055,52.945 30.9,57.1 30.9,59.2 J42.11@29.63,60.47
MCA_UART_RX: J42.7 U7.AN22 | length 62.6
  1-TOP w0.2: U7.AN22@20.32,8.89 20.33,8.9 v1(23.8,8.9)
  8-BOTTOM w0.15: v1(23.8,8.9) 23.8,9.4 21.4,11.8 21.4,18.307 36,32.907 36,59.18 J42.7@34.71,60.47
MCA_UART_TX: J42.5 U7.AN21 | length 65.2
  1-TOP w0.2: U7.AN21@20.32,7.62 v1(20.955,6.985)
  8-BOTTOM w0.15: v1(20.955,6.985) 22.885,6.985 24.3,8.4 24.3,9.5 21.9,11.9 21.9,18.1 36.5,32.7 36.5,48.955 38.5,50.955 38.5,59.2 J42.5@37.3,60.4
MCA_VIN_DET: R22.2 U4.1 U7.AM27 | length 101.9
  1-TOP w0.2: U7.AM27@19.05,15.24 19.6,15.79 v1(19.6,38.7) ; U4.1@88.55,49.35 R22.2@90.235,49.35 ; v1(89.4,45.3) 89.4,49.315
  3-INTOP w0.2: v1(19.6,38.7) 29.7,38.7 31.3,40.3 65.4,40.3 70.4,45.3 v1(89.4,45.3)
MCA_VREF_OUT: J42.18 U7.AM24 | length 49.3
  1-TOP w0.2: v1(18.415,12.065) U7.AM24@19.05,11.43
  6-INBOT w0.2: v1(17.8,27.4) 17.8,40.7 22.01,44.91 J42.18@22.01,57.93
  8-BOTTOM w0.2: v1(17.8,27.4) 17.8,16.5 19.1,15.2 19.1,12.75 v1(18.415,12.065)
MIC_BIAS: C159.2 L32.2 R165.1 U27.45 | length 9.1
  1-TOP w0.2: R165.1@-69.8,35.02 -68.92,35.02 v1(-68.9,35) -68.1,34.2 U27.45@-67.03,34.2 ; C159.2@-69.2,38.86 v1(-69.2,39.54) L32.2@-69.2,40.22
  8-BOTTOM w0.2: v1(-69.2,39.54) -69.2,38.3 -68.9,38 v1(-68.9,35)
MIC_N: L33.1 R167.1 | length 0.9
  1-TOP w0.2: L33.1@-70.3,41.18 R167.1@-70.3,42.12
MIC_P: L32.1 R166.1 | length 0.9
  1-TOP w0.2: L32.1@-69.2,41.18 R166.1@-69.2,42.12
MIKROBUS_ADC: J39.1 J48.9 | length 274
  3-INTOP w0.2: v1@-79.603,-42.697 -78.12,-44.18 -71.827,-44.18 -70.307,-45.7 -61.2,-45.7 -59.7,-47.2 -42.807,-47.2 -41.707,-48.3 -19.007,-48.3 -15.407,-51.9 20.3,-51.9 22.2,-50 26.193,-50 26.893,-50.7 40.4,-50.7 42.8,-48.3 58.8,-48.3 73.6,-33.5 80.8,-33.5 84,-30.3 105.3,-30.3 105.7,-30.7 110,-30.7 110.4,-30.3 112.1,-30.3 114.1,-28.3 114.1,-18.9 112.3,-17.1 J39.1@112.3,-4.725
  8-BOTTOM w0.2: J48.9@-81.2,-1.86 -79.6,-3.46 v1(-79.6,-42.7)
MIKROBUS_I2C_SCL: J40.5 R48.2 | length 77.4
  1-TOP w0.2: R48.2@68.2,20.18 68.2,20.7 68.5,21 74.4,21 74.8,21.4 88.2,21.4 89.1,20.5 v1(92.3,20.5)
  6-INBOT w0.2: v1(92.3,20.5) 92.3,-7.893 101.1,-16.693 101.1,-26.545 J40.5@102.14,-27.585
MIKROBUS_I2C_SDA: J40.6 R49.2 | length 70.5
  1-TOP w0.2: R49.2@68.2,17.12 68.2,16.5 68.4,16.3 72.2,16.3 75.1,13.4 v1(91.7,13.4)
  6-INBOT w0.2: v1(91.7,13.4) 91.7,-8 100.6,-16.9 100.6,-26.585 J40.6@99.6,-27.585
MIKROBUS_INT: J40.2 R50.1 U7.N29 | length 168.3
  1-TOP w0.2: v1(-5.1,21) -5.1,17.8 U7.N29@-5.08,17.78 ; v1(108.5,18.6) 108.5,-6.8 109.76,-8.06 J40.2@109.76,-27.585 R50.1@109.76,-30.2
  3-INTOP w0.2: v1(-5.1,21) 60.8,21 61.8,20 74.3,20 75.7,21.4 99.8,21.4 102.6,18.6 v1(108.5,18.6)
MIKROBUS_PWM: J40.1 J48.10 | length 252.4
  3-INTOP w0.2: v1(-79.1,-42) -77.42,-43.68 -71.62,-43.68 -70.1,-45.2 -60.993,-45.2 -59.493,-46.7 -42.6,-46.7 -41.5,-47.8 -18.8,-47.8 -15.2,-51.4 20.093,-51.4 21.993,-49.5 26.4,-49.5 27.1,-50.2 40.193,-50.2 42.593,-47.8 58.593,-47.8 73.393,-33 80.593,-33 83.793,-29.8 105.6,-29.8 105.9,-30.1 109.7,-30.1 110,-29.8 111.5,-29.8 112.3,-29 J40.1@112.3,-27.585
  8-BOTTOM w0.2: J48.10@-83.74,-1.86 -82.48,-0.6 -80.7,-0.6 -79.1,-2.2 v1(-79.1,-42)
MIKROBUS_RST: J39.2 U7.Y1 | length 130.3
  1-TOP w0.15: v1(3.8,-30.7) 3.8,-17.79 U7.Y1@3.81,-17.78
  3-INTOP w0.2: v1(3.8,-30.7) 50.4,-30.7 51.2,-31.5 78.4,-31.5 98.8,-11.1 103.385,-11.1 J39.2@109.76,-4.725
MIKROBUS_UART_RX: J40.4 J62.3 | length 178.7
  3-INTOP w0.2: J62.3@-64.52,-20.6 -61.92,-23.2 v1(-41.7,-23.2) ; v1(-38.8,-29.3) 1.4,-29.3 3.3,-31.2 44.7,-31.2 46.8,-33.3 52.393,-33.3 53.693,-32 80.037,-32 83.337,-28.7 103.565,-28.7 J40.4@104.68,-27.585
  6-INBOT w0.2: v1(-41.7,-23.2) -41.7,-26.4 v1(-38.8,-29.3)
MIKROBUS_UART_TX: J40.3 J61.3 | length 172.9
  3-INTOP w0.2: J61.3@-54.62,-20.6 -52.5,-20.6 -51.4,-21.7 v1(-42.189,-21.7) ; v1(-39.3,-29.8) 1.193,-29.8 3.093,-31.7 44.493,-31.7 46.593,-33.8 52.6,-33.8 53.9,-32.5 80.244,-32.5 83.544,-29.2 105.605,-29.2 J40.3@107.22,-27.585
  6-INBOT w0.2: v1(-42.189,-21.7) -42.189,-26.911 v1(-39.3,-29.8)
MIPI_CSI1_CLK_N: J30.8 U7.AM14 | length 82.3
  1-TOP w0.15: U7.AM14@19.05,-1.27 v1(19.685,-1.905) ; J30.8@56.9,56.55 56.9,57.175 57.687,57.962 57.812,57.962 57.923,57.851 57.923,54.7
  8-BOTTOM w0.15: v1(19.685,-1.905) 20.143,-2.363 21.55,-2.363 21.625,-2.363 21.713,-2.275 21.713,-1.95 21.8,-1.863 21.975,-1.863 22.063,-1.95 22.063,-2.276 22.15,-2.363 22.325,-2.363 22.413,-2.276 22.413,-2.174 22.5,-2.087 22.675,-2.087 22.763,-2.174 22.763,-2.275 22.851,-2.363 23.125,-2.363 23.437,-2.363 44.2,18.4 44.2,40.201 57.923,53.924 57.923,54.215 57.775,54.363 v1(57.775,54.457)
MIPI_CSI1_CLK_P: J30.7 U7.AM13 | length 82.2
  1-TOP w0.15: U7.AM13@19.05,-2.54 v1(19.685,-3.175) ; J30.7@57.9,60.2 57.9,58.373 58.277,57.996 58.277,54.7
  8-BOTTOM w0.15: v1(19.685,-3.175) 20.143,-2.717 23.584,-2.717 44.554,18.253 44.554,40.054 58.277,53.777 58.277,54.215 58.425,54.363 v1(58.425,54.457)
MIPI_CSI1_DATA0_N: J30.14 U7.AL16 | length 82.3
  1-TOP w0.15: U7.AL16@17.78,1.27 v1(18.415,1.905) ; J30.14@50.9,56.55 50.9,57.175 51.687,57.962 51.812,57.962 51.923,57.851 51.923,54.7
  8-BOTTOM w0.15: v1(18.415,1.905) 18.873,1.447 19.675,1.447 19.75,1.447 19.838,1.535 19.838,1.843 19.925,1.93 20.1,1.93 20.188,1.843 20.188,1.534 20.275,1.447 20.45,1.447 20.538,1.534 20.538,1.651 20.625,1.739 20.8,1.739 20.888,1.651 20.888,1.535 20.976,1.447 21.396,1.447 23.047,1.447 41.3,19.7 41.3,46.001 46.021,50.722 46.021,53.668 46.507,54.154 47.249,54.154 47.754,53.649 47.754,52.922 48.147,52.529 50.828,52.529 51.923,53.624 51.923,54.215 51.775,54.363 v1(51.775,54.457)
MIPI_CSI1_DATA0_P: J30.13 U7.AL15 | length 82.3
  1-TOP w0.15: U7.AL15@17.78,0 v1(18.415,0.635) ; J30.13@51.9,60.2 51.9,58.373 52.277,57.996 52.277,54.7
  8-BOTTOM w0.15: v1(18.415,0.635) 18.873,1.093 23.194,1.093 41.654,19.553 41.654,45.854 46.375,50.575 46.375,53.522 46.653,53.8 47.103,53.8 47.4,53.503 47.4,52.775 48,52.175 50.975,52.175 52.277,53.477 52.277,54.215 52.425,54.363 v1(52.425,54.457)
MIPI_CSI1_DATA1_N: J30.11 U7.AL13 | length 82.5
  1-TOP w0.15: U7.AL13@17.78,-2.54 v1(18.415,-1.905) ; 53.523,54.7 53.523,57.996 53.9,58.373 J30.11@53.9,60.2
  8-BOTTOM w0.15: v1(18.415,-1.905) 18.415,-2.288 18.49,-2.363 18.8,-2.363 18.9,-2.263 18.9,-1.299 19.353,-0.846 21.311,-0.846 21.35,-0.807 22.05,-0.807 22.089,-0.846 22.554,-0.846 42.7,19.3 42.7,44.975 47.279,49.554 50.229,49.554 53.523,52.848 53.523,54.215 53.375,54.363 v1(53.375,54.457) v1@53.523,54.309
MIPI_CSI1_DATA1_P: J30.10 U7.AL12 | length 82.5
  1-TOP w0.15: U7.AL12@17.78,-3.81 v1(18.415,-3.175) ; 53.877,54.7 53.877,57.851 53.988,57.962 54.113,57.962 54.9,57.175 J30.10@54.9,56.55
  8-BOTTOM w0.15: v1(18.415,-3.175) 18.415,-2.792 18.49,-2.717 18.947,-2.717 19.254,-2.41 19.254,-1.446 19.5,-1.2 22.701,-1.2 43.054,19.153 43.054,44.828 47.426,49.2 50.376,49.2 53.877,52.701 53.877,54.215 53.924,54.262 54.025,54.363 v1(54.025,54.457) v1@53.877,54.309
MIPI_CSI1_I2C_SCL: J30.3 R184.2 | length 41
  1-TOP w0.2: v1(61.9,54.7) J30.3@61.9,60.2 ; R184.2@64.2,20.18 v1(64.2,20.8)
  6-INBOT w0.2: v1(61.9,54.7) 61.9,53.3 63.3,51.9 63.3,23.9 64.2,23 v1(64.2,20.8)
MIPI_CSI1_I2C_SDA: J30.2 R186.2 | length 41.7
  1-TOP w0.2: v1(62.9,54.7) J30.2@62.9,56.55 ; v1(64.2,16.5) R186.2@64.2,17.12
  6-INBOT w0.2: v1(62.9,54.7) 62.9,54 62.9,53.9 62.9,53.007 63.8,52.107 63.8,24.1 64.7,23.2 64.7,19.5 64.2,19 v1(64.2,16.5) v1@64.2,16.4
MIPI_CSI1_RESET_N: J30.5 U7.E28 | length 148.2
  1-TOP w0.2: v1(-23.9,13.9) -23.1,13.9 -19.9,17.1 -15.83,17.1 U7.E28@-15.24,16.51 ; v1(59.9,50.5) J30.5@59.9,60.762
  3-INTOP w0.2: v1(-30.8,46.4) -2.9,46.4 1.2,50.5 v1(59.9,50.5)
  6-INBOT w0.2: v1(-30.8,46.4) -30.8,43.1 -23.9,36.2 v1(-23.9,13.9)
MIPI_DSI1_CLK_N: U7.AN6 U15.2 | length 78.8
  1-TOP w0.15: U15.2@19.4,-52.255 19.423,-52.232 19.423,-51.376 21.1,-49.699 21.1,-48.101 20.046,-47.047 20.046,-26.779 20.623,-26.202 21.725,-25.1 28.079,-25.1 28.246,-24.933 28.246,-24.235 28.065,-24.054 23.182,-24.054 22.8,-23.672 22.8,-22.772 23.172,-22.4 27.98,-22.4 28.146,-22.234 28.146,-21.547 27.953,-21.354 22.853,-21.354 22.546,-21.047 22.546,-20.153 22.899,-19.8 28.2,-19.8 28.846,-19.154 28.846,-13.122 26.696,-10.972 22.475,-10.972 22.4,-10.972 22.312,-11.06 22.312,-11.297 22.26,-11.35 22.015,-11.35 21.962,-11.297 21.962,-11.06 21.874,-10.972 21.325,-10.972 21,-10.972 20.778,-10.972 U7.AN6@20.32,-11.43
MIPI_DSI1_CLK_P: U7.AN7 U15.1 | length 78.8
  1-TOP w0.15: U15.1@19.8,-52.255 19.777,-52.232 19.777,-51.523 21.454,-49.846 21.454,-47.954 20.4,-46.9 20.4,-26.926 21.872,-25.454 28.226,-25.454 28.6,-25.08 28.6,-24.088 28.212,-23.7 23.328,-23.7 23.154,-23.526 23.154,-22.919 23.319,-22.754 28.127,-22.754 28.5,-22.381 28.5,-21.4 28.1,-21 23,-21 22.9,-20.9 22.9,-20.3 23.046,-20.154 28.347,-20.154 29.2,-19.301 29.2,-12.975 26.843,-10.618 20.778,-10.618 U7.AN7@20.32,-10.16
MIPI_DSI1_DATA0_N: U7.AN9 U16.4 | length 75.6
  1-TOP w0.15: U7.AN9@20.32,-7.62 20.778,-7.162 21.657,-7.162 22.082,-7.162 22.17,-7.25 22.17,-7.478 22.24,-7.548 22.45,-7.548 22.52,-7.478 22.52,-7.25 22.608,-7.162 23.282,-7.162 24.836,-7.162 29.746,-12.072 29.746,-25.753 28.999,-26.5 22.175,-26.5 21.8,-26.875 21.8,-28.595 22.259,-29.054 23.252,-29.054 23.654,-28.652 23.654,-28.246 23.8,-28.1 28.885,-28.1 29.346,-28.561 29.346,-29.454 21.946,-36.854 21.946,-46.477 v1(21.823,-46.6) ; v1(25.8,-48.323) 25.923,-48.2 27.399,-48.2 27.723,-48.524 27.723,-50.832 U16.4@27.7,-50.855
  8-BOTTOM w0.15: v1(21.823,-46.6) v1@21.946,-46.723 ; v1@21.946,-46.661 v1@21.946,-46.723 ; v1(25.8,-48.323) 25.677,-48.2 22.399,-48.2 21.946,-47.747 v1@21.946,-46.723
MIPI_DSI1_DATA0_P: U7.AN10 U16.3 | length 75.5
  1-TOP w0.15: U7.AN10@20.32,-6.35 20.778,-6.808 24.983,-6.808 30.1,-11.925 30.1,-25.9 29.146,-26.854 22.322,-26.854 22.154,-27.022 22.154,-28.448 22.406,-28.7 23.105,-28.7 23.3,-28.505 23.3,-28.099 23.653,-27.746 29.031,-27.746 29.7,-28.415 29.7,-29.601 22.3,-37.001 22.3,-46.477 v1(22.423,-46.6) ; v1(25.8,-47.723) 25.923,-47.846 27.546,-47.846 28.077,-48.377 28.077,-50.832 U16.3@28.1,-50.855
  8-BOTTOM w0.15: v1(22.423,-46.6) 22.3,-46.723 22.3,-47.6 22.546,-47.846 25.677,-47.846 v1(25.8,-47.723)
MIPI_DSI1_DATA1_N: U7.AN12 U16.6 | length 78.8
  1-TOP w0.15: U7.AN12@20.32,-3.81 20.778,-3.352 21.575,-3.352 21.65,-3.352 22.075,-3.352 22.163,-3.44 22.163,-3.673 22.215,-3.726 22.46,-3.726 22.513,-3.673 22.513,-3.44 22.601,-3.352 23,-3.352 23.125,-3.352 23.849,-3.352 24.254,-2.947 24.254,-0.727 24.452,-0.529 25.276,-0.529 25.5,-0.753 25.5,-5.814 25.911,-6.225 26.936,-6.225 27.354,-5.807 27.354,-1.338 27.538,-1.154 28.178,-1.154 28.396,-1.372 28.396,-3.897 28.799,-4.3 30.499,-4.3 30.7,-4.501 30.7,-5.7 30.7,-29.599 23.146,-37.153 23.146,-45.246 24.1,-46.2 24.1,-49.3 24.5,-49.7 26.5,-49.7 26.923,-50.123 26.923,-50.832 U16.6@26.9,-50.855
MIPI_DSI1_DATA1_P: U7.AN13 U16.5 | length 78.8
  1-TOP w0.15: U7.AN13@20.32,-2.54 20.778,-2.998 23.702,-2.998 23.9,-2.8 23.9,-0.58 24.305,-0.175 25.422,-0.175 25.854,-0.607 25.854,-5.667 26.058,-5.871 26.789,-5.871 27,-5.66 27,-1.192 27.392,-0.8 28.325,-0.8 28.75,-1.225 28.75,-3.75 28.946,-3.946 30.646,-3.946 31.054,-4.354 31.054,-29.746 23.5,-37.3 23.5,-45.099 24.454,-46.053 24.454,-49.153 24.647,-49.346 26.647,-49.346 27.277,-49.976 27.277,-50.832 U16.5@27.3,-50.855
MIPI_DSI1_DATA2_N: U7.AN15 U15.4 | length 75.5
  1-TOP w0.15: U15.4@18.6,-52.255 18.623,-52.232 18.623,-50.876 19.523,-49.976 19.523,-49.7 v1(19.4,-49.577) ; U7.AN15@20.32,0 20.778,0.458 21.325,0.458 21.75,0.458 21.838,0.37 21.838,0.134 21.89,0.081 22.135,0.081 22.188,0.134 22.188,0.37 22.276,0.458 22.475,0.458 22.759,0.458 23.254,0.953 23.254,3.054 23.5,3.3 24.074,3.3 24.3,3.074 24.3,0.899 24.741,0.458 27.966,0.458 31.7,-3.276 31.7,-30.899 24.9,-37.699 24.9,-44.777 v1(24.777,-44.9)
  8-BOTTOM w0.15: v1(19.4,-49.577) 19.523,-49.454 19.523,-46.701 20.724,-45.5 24.7,-45.5 24.9,-45.3 24.9,-45.023 v1(24.777,-44.9)
MIPI_DSI1_DATA2_P: U7.AN16 U15.3 | length 75.5
  1-TOP w0.15: U15.3@19,-52.255 18.977,-52.232 18.977,-51.023 19.877,-50.123 19.877,-49.7 v1(20,-49.577) ; U7.AN16@20.32,1.27 20.778,0.812 22.612,0.812 22.9,1.1 22.9,3.201 23.353,3.654 24.221,3.654 24.654,3.221 24.654,1.046 24.9,0.8 28.125,0.8 32.054,-3.129 32.054,-31.046 25.254,-37.846 25.254,-44.777 v1(25.377,-44.9)
  8-BOTTOM w0.15: v1(20,-49.577) 19.877,-49.454 19.877,-46.848 20.871,-45.854 24.847,-45.854 25.254,-45.447 25.254,-45.023 v1(25.377,-44.9)
MIPI_DSI1_DATA3_N: U7.AN18 U15.6 | length 75.7
  1-TOP w0.15: v1(17.7,-46.777) 17.823,-46.9 U15.6@17.823,-52.255 ; U7.AN18@20.32,3.81 20.778,4.268 21,4.268 21.425,4.268 21.513,4.18 21.513,3.952 21.583,3.882 21.793,3.882 21.863,3.952 21.863,4.18 21.951,4.268 22.5,4.268 25.932,4.268 32.7,-2.5 32.7,-31.799 26.4,-38.099 26.4,-42.577 v1(26.277,-42.7) v1@26.4,-42.823
  8-BOTTOM w0.15: v1(17.7,-46.777) 17.823,-46.654 17.823,-45.953 20.376,-43.4 26.199,-43.4 26.4,-43.199 26.4,-42.823 v1(26.277,-42.7)
MIPI_DSI1_DATA3_P: U7.AN19 U15.5 | length 75.5
  1-TOP w0.15: U15.5@18.177,-52.255 18.177,-46.9 v1(18.3,-46.777) ; U7.AN19@20.32,5.08 20.778,4.622 26.079,4.622 33.054,-2.353 33.054,-31.946 26.754,-38.246 26.754,-42.577 v1(26.877,-42.7)
  8-BOTTOM w0.15: v1(18.3,-46.777) 18.177,-46.654 18.177,-46.1 20.523,-43.754 26.346,-43.754 26.754,-43.346 26.754,-42.823 v1(26.877,-42.7)
MIPI_EXT_CLK_N: J29.33 U15.23 | length 21.1
  1-TOP w0.15: U15.23@20.495,-52.9 21.05,-52.9 21.073,-52.923 21.877,-52.923 v1(22,-52.8) ; v1(30.623,-57.5) 30.6,-57.5 30.5,-57.6 30.5,-58.3 31.6,-59.4 31.6,-60.999 32.277,-61.676 32.277,-62.09 32.35,-62.163 J29.33@32.35,-62.85
  8-BOTTOM w0.15: v1(22,-52.8) 22.123,-52.923 22.523,-52.923 23.054,-53.454 23.054,-56.254 24.6,-57.8 27.699,-57.8 28.853,-56.646 30.146,-56.646 30.5,-57 30.5,-57.377 v1(30.623,-57.5)
MIPI_EXT_CLK_P: J29.32 U15.22 | length 21.1
  1-TOP w0.15: U15.22@20.495,-53.3 21.05,-53.3 21.073,-53.277 21.877,-53.277 v1(22,-53.4) ; v1(30.023,-57.5) 30.046,-57.5 30.146,-57.6 30.146,-58.447 31.246,-59.547 31.246,-61.146 31.923,-61.823 31.923,-62.09 31.85,-62.163 J29.32@31.85,-62.85
  8-BOTTOM w0.15: v1(22,-53.4) 22.123,-53.277 22.376,-53.277 22.7,-53.601 22.7,-54.19 22.7,-54.615 22.612,-54.703 22.377,-54.703 22.325,-54.755 22.325,-55 22.377,-55.053 22.612,-55.053 22.7,-55.141 22.7,-55.282 22.7,-56.401 24.453,-58.154 27.846,-58.154 29,-57 29.999,-57 30.146,-57.147 30.146,-57.377 v1(30.023,-57.5)
MIPI_EXT_DATA0_N: J29.36 U16.21 | length 24.4
  1-TOP w0.15: U16.21@29.595,-52.3 29.618,-52.323 30.2,-52.323 30.4,-52.123 30.4,-48.775 30.875,-48.3 33.606,-48.3 34.025,-48.719 34.025,-50.412 33.637,-50.8 32.5,-50.8 32.3,-51 32.3,-60.3 33.777,-61.777 33.777,-62.09 33.85,-62.163 J29.36@33.85,-62.85
MIPI_EXT_DATA0_P: J29.35 U16.20 | length 24.4
  1-TOP w0.15: U16.20@29.595,-52.7 29.618,-52.677 30.347,-52.677 30.754,-52.27 30.754,-52.171 30.754,-51.746 30.842,-51.658 31.076,-51.658 31.128,-51.605 31.128,-51.36 31.076,-51.308 30.842,-51.308 30.754,-51.22 30.754,-50.976 30.754,-48.922 31.022,-48.654 33.459,-48.654 33.671,-48.866 33.671,-50.266 33.491,-50.446 32.353,-50.446 31.946,-50.853 31.946,-60.447 33.423,-61.924 33.423,-62.09 33.35,-62.163 J29.35@33.35,-62.85
MIPI_EXT_DATA1_N: J29.30 U16.18 | length 21.1
  1-TOP w0.15: U16.18@28.9,-53.345 28.9,-53.9 28.973,-53.973 28.973,-54.347 29.28,-54.654 29.875,-54.654 29.963,-54.742 29.963,-54.831 30.015,-54.883 30.26,-54.883 30.313,-54.831 30.313,-54.742 30.401,-54.654 30.977,-54.654 v1(31.1,-54.777) ; v1(29.4,-56.023) 29.4,-56 29.3,-55.9 29.001,-55.9 28.9,-56.001 28.9,-58.099 30.777,-59.976 30.777,-62.09 30.85,-62.163 J29.30@30.85,-62.85
  8-BOTTOM w0.15: v1(29.4,-56.023) 29.277,-55.9 28.449,-55.9 28,-55.451 28,-54.5 28.4,-54.1 29.401,-54.1 30.5,-55.199 30.5,-55.399 31.047,-55.946 31.553,-55.946 31.85,-55.649 31.85,-54.876 31.662,-54.688 31.189,-54.688 v1(31.1,-54.777)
